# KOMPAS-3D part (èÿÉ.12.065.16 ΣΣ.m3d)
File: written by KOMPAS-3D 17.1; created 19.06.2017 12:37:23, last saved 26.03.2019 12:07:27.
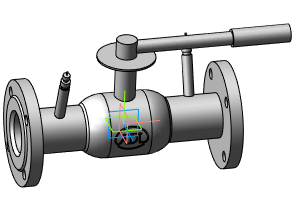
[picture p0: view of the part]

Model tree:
1. Операция без истории:2  (labels: Сталь 20  ГОСТ 1050-88)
